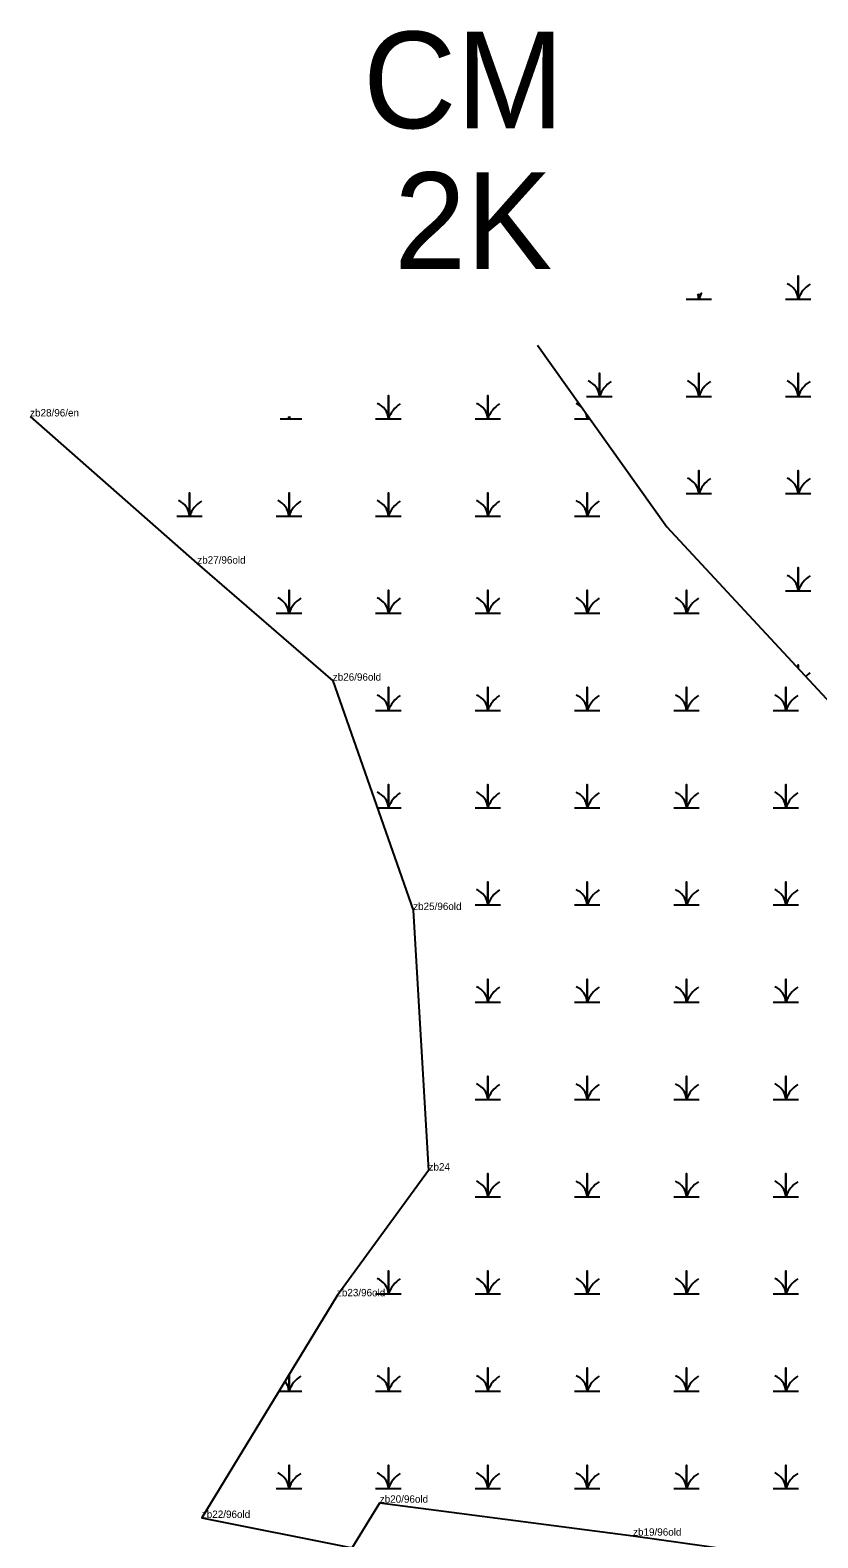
# Model space of a CAD drawing. Extents: x 2072529 to 2268796, y 436423 to 470406.
# Drawn here: x 2251149 to 2251682, y 438852 to 439872 of the extents above; entities that cross this region are included whole.
import ezdxf

# ---------------------------------------------------------------- set-up
doc = ezdxf.new("R2010")
doc.units = 0
for name, color, linetype in [('Default', 7, 'Continuous'), ('Exist Environmental Wetland Boundary', 7, 'Continuous'), ('Exist Environmental Wetland Boundary Cogo Comment', 7, 'Continuous'), ('Exist Hydro Jurisdictional Stream or Body of Water NEU Mitigable', 7, 'Continuous'), ('Exist Hydro Swamp or Marsh', 7, 'Continuous'), ('Old_Level_20', 7, 'Continuous')]:
    doc.layers.add(name, color=color, linetype=linetype)

msp = doc.modelspace()

# ---------------------------------------------------------------- linework, layer by layer
at = {"layer": 'Exist Environmental Wetland Boundary'}
msp.add_lwpolyline([(2251148.9, 439610.5), (2251262, 439510.9), (2251353.7, 439431.7), (2251408.1, 439276.5), (2251418.5, 439100.2), (2251356.5, 439015.1), (2251265.1, 438865.1), (2251366.8, 438844.8), (2251385.5, 438875.4), (2251556.9, 438853.1), (2251718.8, 438830.1), (2251868.4, 438640), (2251940.7, 438572.9), (2252098.5, 438426.7), (2252083, 438409.3), (2252090.3, 438402.8), (2252096.8, 438411.4), (2252129.6, 438370.7)], dxfattribs=at)
at = {"layer": 'Exist Hydro Jurisdictional Stream or Body of Water NEU Mitigable'}
for p, q in [((2251492.3, 439658.8), (2251579.7, 439535.8)), ((2251579.7, 439535.8), (2251746.6, 439355.9))]:
    msp.add_line(p, q, dxfattribs=at)
at = {"layer": 'Exist Hydro Swamp or Marsh'}
for points in [[(2251660, 439689.9), (2251668.6, 439689.9), (2251668.6, 439705.6), (2251668.6, 439689.9), (2251677.2, 439689.9)], [(2251592.8, 439689.9), (2251601.4, 439689.9), (2251601.4, 439693.5)], [(2251601.4, 439693.5), (2251601.4, 439689.9), (2251610, 439689.9)], [(2251525.5, 439624.1), (2251534.1, 439624.1), (2251534.1, 439639.8), (2251534.1, 439624.1), (2251542.7, 439624.1)], [(2251592.8, 439624.1), (2251601.4, 439624.1), (2251601.4, 439639.8), (2251601.4, 439624.1), (2251610, 439624.1)], [(2251660, 439624.1), (2251668.6, 439624.1), (2251668.6, 439639.8), (2251668.6, 439624.1), (2251677.2, 439624.1)], [(2251382.7, 439608.9), (2251391.3, 439608.9), (2251391.3, 439624.6), (2251391.3, 439608.9), (2251399.9, 439608.9)], [(2251450, 439608.9), (2251458.6, 439608.9), (2251458.6, 439624.6), (2251458.6, 439608.9), (2251467.2, 439608.9)], [(2251318.1, 439608.9), (2251324.1, 439608.9), (2251324.1, 439610.4)], [(2251324.1, 439610.4), (2251324.1, 439608.9), (2251332.7, 439608.9)], [(2251517.2, 439608.9), (2251525.8, 439608.9), (2251525.8, 439611.6)], [(2251525.8, 439611.6), (2251525.8, 439608.9), (2251527.8, 439608.9)], [(2251592.8, 439558.3), (2251601.4, 439558.3), (2251601.4, 439574), (2251601.4, 439558.3), (2251610, 439558.3)], [(2251660, 439558.3), (2251668.6, 439558.3), (2251668.6, 439574), (2251668.6, 439558.3), (2251677.2, 439558.3)], [(2251248.2, 439543.1), (2251256.8, 439543.1), (2251256.8, 439558.8), (2251256.8, 439543.1), (2251265.4, 439543.1)], [(2251315.5, 439543.1), (2251324.1, 439543.1), (2251324.1, 439558.8), (2251324.1, 439543.1), (2251332.7, 439543.1)], [(2251382.7, 439543.1), (2251391.3, 439543.1), (2251391.3, 439558.8), (2251391.3, 439543.1), (2251399.9, 439543.1)], [(2251450, 439543.1), (2251458.6, 439543.1), (2251458.6, 439558.8), (2251458.6, 439543.1), (2251467.2, 439543.1)], [(2251517.2, 439543.1), (2251525.8, 439543.1), (2251525.8, 439558.8), (2251525.8, 439543.1), (2251534.4, 439543.1)], [(2251660, 439492.5), (2251668.6, 439492.5), (2251668.6, 439508.2), (2251668.6, 439492.5), (2251677.2, 439492.5)], [(2251315.5, 439477.3), (2251324.1, 439477.3), (2251324.1, 439493), (2251324.1, 439477.3), (2251332.7, 439477.3)], [(2251382.7, 439477.3), (2251391.3, 439477.3), (2251391.3, 439493), (2251391.3, 439477.3), (2251399.9, 439477.3)], [(2251450, 439477.3), (2251458.6, 439477.3), (2251458.6, 439493), (2251458.6, 439477.3), (2251467.2, 439477.3)], [(2251517.2, 439477.3), (2251525.8, 439477.3), (2251525.8, 439493), (2251525.8, 439477.3), (2251534.4, 439477.3)], [(2251584.5, 439477.3), (2251593.1, 439477.3), (2251593.1, 439493), (2251593.1, 439477.3), (2251601.7, 439477.3)], [(2251668.6, 439440), (2251668.6, 439442.4), (2251668.6, 439440)], [(2251382.7, 439411.5), (2251391.3, 439411.5), (2251391.3, 439427.2), (2251391.3, 439411.5), (2251399.9, 439411.5)], [(2251450, 439411.5), (2251458.6, 439411.5), (2251458.6, 439427.2), (2251458.6, 439411.5), (2251467.2, 439411.5)], [(2251517.2, 439411.5), (2251525.8, 439411.5), (2251525.8, 439427.2), (2251525.8, 439411.5), (2251534.4, 439411.5)], [(2251584.5, 439411.5), (2251593.1, 439411.5), (2251593.1, 439427.2), (2251593.1, 439411.5), (2251601.7, 439411.5)], [(2251651.7, 439411.5), (2251660.3, 439411.5), (2251660.3, 439427.2), (2251660.3, 439411.5), (2251668.9, 439411.5)], [(2251383.8, 439345.7), (2251391.3, 439345.7), (2251391.3, 439361.4), (2251391.3, 439345.7), (2251399.9, 439345.7)], [(2251450, 439345.7), (2251458.6, 439345.7), (2251458.6, 439361.4), (2251458.6, 439345.7), (2251467.2, 439345.7)], [(2251517.2, 439345.7), (2251525.8, 439345.7), (2251525.8, 439361.4), (2251525.8, 439345.7), (2251534.4, 439345.7)], [(2251584.5, 439345.7), (2251593.1, 439345.7), (2251593.1, 439361.4), (2251593.1, 439345.7), (2251601.7, 439345.7)], [(2251651.7, 439345.7), (2251660.3, 439345.7), (2251660.3, 439361.4), (2251660.3, 439345.7), (2251668.9, 439345.7)], [(2251450, 439279.9), (2251458.6, 439279.9), (2251458.6, 439295.6), (2251458.6, 439279.9), (2251467.2, 439279.9)], [(2251517.2, 439279.9), (2251525.8, 439279.9), (2251525.8, 439295.6), (2251525.8, 439279.9), (2251534.4, 439279.9)], [(2251584.5, 439279.9), (2251593.1, 439279.9), (2251593.1, 439295.6), (2251593.1, 439279.9), (2251601.7, 439279.9)], [(2251651.7, 439279.9), (2251660.3, 439279.9), (2251660.3, 439295.6), (2251660.3, 439279.9), (2251668.9, 439279.9)], [(2251450, 439214.1), (2251458.6, 439214.1), (2251458.6, 439229.8), (2251458.6, 439214.1), (2251467.2, 439214.1)], [(2251517.2, 439214.1), (2251525.8, 439214.1), (2251525.8, 439229.8), (2251525.8, 439214.1), (2251534.4, 439214.1)], [(2251584.5, 439214.1), (2251593.1, 439214.1), (2251593.1, 439229.8), (2251593.1, 439214.1), (2251601.7, 439214.1)], [(2251651.7, 439214.1), (2251660.3, 439214.1), (2251660.3, 439229.8), (2251660.3, 439214.1), (2251668.9, 439214.1)], [(2251450, 439148.3), (2251458.6, 439148.3), (2251458.6, 439164), (2251458.6, 439148.3), (2251467.2, 439148.3)], [(2251517.2, 439148.3), (2251525.8, 439148.3), (2251525.8, 439164), (2251525.8, 439148.3), (2251534.4, 439148.3)], [(2251584.5, 439148.3), (2251593.1, 439148.3), (2251593.1, 439164), (2251593.1, 439148.3), (2251601.7, 439148.3)], [(2251651.7, 439148.3), (2251660.3, 439148.3), (2251660.3, 439164), (2251660.3, 439148.3), (2251668.9, 439148.3)], [(2251450, 439082.5), (2251458.6, 439082.5), (2251458.6, 439098.2), (2251458.6, 439082.5), (2251467.2, 439082.5)], [(2251517.2, 439082.5), (2251525.8, 439082.5), (2251525.8, 439098.2), (2251525.8, 439082.5), (2251534.4, 439082.5)], [(2251584.5, 439082.5), (2251593.1, 439082.5), (2251593.1, 439098.2), (2251593.1, 439082.5), (2251601.7, 439082.5)], [(2251651.7, 439082.5), (2251660.3, 439082.5), (2251660.3, 439098.2), (2251660.3, 439082.5), (2251668.9, 439082.5)], [(2251382.7, 439016.7), (2251391.3, 439016.7), (2251391.3, 439032.4), (2251391.3, 439016.7), (2251399.9, 439016.7)], [(2251450, 439016.7), (2251458.6, 439016.7), (2251458.6, 439032.4), (2251458.6, 439016.7), (2251467.2, 439016.7)], [(2251517.2, 439016.7), (2251525.8, 439016.7), (2251525.8, 439032.4), (2251525.8, 439016.7), (2251534.4, 439016.7)], [(2251584.5, 439016.7), (2251593.1, 439016.7), (2251593.1, 439032.4), (2251593.1, 439016.7), (2251601.7, 439016.7)], [(2251651.7, 439016.7), (2251660.3, 439016.7), (2251660.3, 439032.4), (2251660.3, 439016.7), (2251668.9, 439016.7)], [(2251382.7, 438950.9), (2251391.3, 438950.9), (2251391.3, 438966.6), (2251391.3, 438950.9), (2251399.9, 438950.9)], [(2251450, 438950.9), (2251458.6, 438950.9), (2251458.6, 438966.6), (2251458.6, 438950.9), (2251467.2, 438950.9)], [(2251517.2, 438950.9), (2251525.8, 438950.9), (2251525.8, 438966.6), (2251525.8, 438950.9), (2251534.4, 438950.9)], [(2251584.5, 438950.9), (2251593.1, 438950.9), (2251593.1, 438966.6), (2251593.1, 438950.9), (2251601.7, 438950.9)], [(2251651.7, 438950.9), (2251660.3, 438950.9), (2251660.3, 438966.6), (2251660.3, 438950.9), (2251668.9, 438950.9)], [(2251317.3, 438950.9), (2251324.1, 438950.9), (2251324.1, 438961.9)], [(2251324.1, 438961.9), (2251324.1, 438950.9), (2251332.7, 438950.9)], [(2251315.5, 438885.1), (2251324.1, 438885.1), (2251324.1, 438900.8), (2251324.1, 438885.1), (2251332.7, 438885.1)], [(2251382.7, 438885.1), (2251391.3, 438885.1), (2251391.3, 438900.8), (2251391.3, 438885.1), (2251399.9, 438885.1)], [(2251450, 438885.1), (2251458.6, 438885.1), (2251458.6, 438900.8), (2251458.6, 438885.1), (2251467.2, 438885.1)], [(2251517.2, 438885.1), (2251525.8, 438885.1), (2251525.8, 438900.8), (2251525.8, 438885.1), (2251534.4, 438885.1)], [(2251584.5, 438885.1), (2251593.1, 438885.1), (2251593.1, 438900.8), (2251593.1, 438885.1), (2251601.7, 438885.1)], [(2251651.7, 438885.1), (2251660.3, 438885.1), (2251660.3, 438900.8), (2251660.3, 438885.1), (2251668.9, 438885.1)]]:
    msp.add_lwpolyline(points, dxfattribs=at)
for centre, radius, start, end in [((2251589.1, 439689), 12.3, 4.1403, 20.6339), ((2251619.6, 439683.8), 19.2, 147.1842, 161.6222), ((2251656.4, 439689), 12.3, 4.1403, 67.535), ((2251686.9, 439683.8), 19.2, 122.1274, 161.6222), ((2251521.9, 439623.2), 12.3, 4.1403, 67.535), ((2251552.4, 439618), 19.2, 122.1274, 161.6222), ((2251589.1, 439623.2), 12.3, 4.1403, 67.535), ((2251619.6, 439618), 19.2, 122.1274, 161.6222), ((2251656.4, 439623.2), 12.3, 4.1403, 67.535), ((2251686.9, 439618), 19.2, 122.1274, 161.6222), ((2251379.1, 439608), 12.3, 4.1403, 67.535), ((2251409.6, 439602.8), 19.2, 122.1274, 161.6222), ((2251446.3, 439608), 12.3, 4.1403, 67.535), ((2251476.8, 439602.8), 19.2, 122.1274, 161.6222), ((2251513.6, 439608), 12.3, 45.4287, 67.535), ((2251311.8, 439608), 12.3, 4.1403, 10.9704), ((2251342.3, 439602.8), 19.2, 156.2744, 161.6222), ((2251513.6, 439608), 12.3, 4.1403, 25.3582), ((2251544.1, 439602.8), 19.2, 155.9212, 161.6222), ((2251589.1, 439557.4), 12.3, 4.1403, 67.535), ((2251619.6, 439552.2), 19.2, 122.1274, 161.6222), ((2251656.4, 439557.4), 12.3, 4.1403, 67.535), ((2251686.9, 439552.2), 19.2, 122.1274, 161.6222), ((2251244.6, 439542.2), 12.3, 4.1403, 67.535), ((2251275.1, 439537), 19.2, 122.1274, 161.6222), ((2251311.8, 439542.2), 12.3, 4.1403, 67.535), ((2251342.3, 439537), 19.2, 122.1274, 161.6222), ((2251379.1, 439542.2), 12.3, 4.1403, 67.535), ((2251409.6, 439537), 19.2, 122.1274, 161.6222), ((2251446.3, 439542.2), 12.3, 4.1403, 67.535), ((2251476.8, 439537), 19.2, 122.1274, 161.6222), ((2251513.6, 439542.2), 12.3, 4.1403, 67.535), ((2251544.1, 439537), 19.2, 122.1274, 161.6222), ((2251656.4, 439491.6), 12.3, 4.1403, 67.535), ((2251686.9, 439486.4), 19.2, 122.1274, 161.6222), ((2251311.8, 439476.4), 12.3, 4.1403, 67.535), ((2251342.3, 439471.2), 19.2, 122.1274, 161.6222), ((2251379.1, 439476.4), 12.3, 4.1403, 67.535), ((2251409.6, 439471.2), 19.2, 122.1274, 161.6222), ((2251446.3, 439476.4), 12.3, 4.1403, 67.535), ((2251476.8, 439471.2), 19.2, 122.1274, 161.6222), ((2251513.6, 439476.4), 12.3, 4.1403, 67.535), ((2251544.1, 439471.2), 19.2, 122.1274, 161.6222), ((2251580.8, 439476.4), 12.3, 4.1403, 67.535), ((2251611.3, 439471.2), 19.2, 122.1274, 161.6222), ((2251686.9, 439420.6), 19.2, 122.1274, 133.4343), ((2251379.1, 439410.6), 12.3, 4.1403, 67.535), ((2251409.6, 439405.4), 19.2, 122.1274, 161.6222), ((2251446.3, 439410.6), 12.3, 4.1403, 67.535), ((2251476.8, 439405.4), 19.2, 122.1274, 161.6222), ((2251513.6, 439410.6), 12.3, 4.1403, 67.535), ((2251544.1, 439405.4), 19.2, 122.1274, 161.6222), ((2251580.8, 439410.6), 12.3, 4.1403, 67.535), ((2251611.3, 439405.4), 19.2, 122.1274, 161.6222), ((2251648.1, 439410.6), 12.3, 4.1403, 67.535), ((2251678.6, 439405.4), 19.2, 122.1274, 161.6222), ((2251379.1, 439344.8), 12.3, 4.1403, 67.535), ((2251409.6, 439339.6), 19.2, 122.1274, 161.6222), ((2251446.3, 439344.8), 12.3, 4.1403, 67.535), ((2251476.8, 439339.6), 19.2, 122.1274, 161.6222), ((2251513.6, 439344.8), 12.3, 4.1403, 67.535), ((2251544.1, 439339.6), 19.2, 122.1274, 161.6222), ((2251580.8, 439344.8), 12.3, 4.1403, 67.535), ((2251611.3, 439339.6), 19.2, 122.1274, 161.6222), ((2251648.1, 439344.8), 12.3, 4.1403, 67.535), ((2251678.6, 439339.6), 19.2, 122.1274, 161.6222), ((2251446.3, 439279), 12.3, 4.1403, 67.535), ((2251476.8, 439273.8), 19.2, 122.1274, 161.6222), ((2251513.6, 439279), 12.3, 4.1403, 67.535), ((2251544.1, 439273.8), 19.2, 122.1274, 161.6222), ((2251580.8, 439279), 12.3, 4.1403, 67.535), ((2251611.3, 439273.8), 19.2, 122.1274, 161.6222), ((2251648.1, 439279), 12.3, 4.1403, 67.535), ((2251678.6, 439273.8), 19.2, 122.1274, 161.6222), ((2251446.3, 439213.2), 12.3, 4.1403, 67.535), ((2251476.8, 439208), 19.2, 122.1274, 161.6222), ((2251513.6, 439213.2), 12.3, 4.1403, 67.535), ((2251544.1, 439208), 19.2, 122.1274, 161.6222), ((2251580.8, 439213.2), 12.3, 4.1403, 67.535), ((2251611.3, 439208), 19.2, 122.1274, 161.6222), ((2251648.1, 439213.2), 12.3, 4.1403, 67.535), ((2251678.6, 439208), 19.2, 122.1274, 161.6222), ((2251446.3, 439147.4), 12.3, 4.1403, 67.535), ((2251476.8, 439142.2), 19.2, 122.1274, 161.6222), ((2251513.6, 439147.4), 12.3, 4.1403, 67.535), ((2251544.1, 439142.2), 19.2, 122.1274, 161.6222), ((2251580.8, 439147.4), 12.3, 4.1403, 67.535), ((2251611.3, 439142.2), 19.2, 122.1274, 161.6222), ((2251648.1, 439147.4), 12.3, 4.1403, 67.535), ((2251678.6, 439142.2), 19.2, 122.1274, 161.6222), ((2251446.3, 439081.6), 12.3, 4.1403, 67.535), ((2251476.8, 439076.4), 19.2, 122.1274, 161.6222), ((2251513.6, 439081.6), 12.3, 4.1403, 67.535), ((2251544.1, 439076.4), 19.2, 122.1274, 161.6222), ((2251580.8, 439081.6), 12.3, 4.1403, 67.535), ((2251611.3, 439076.4), 19.2, 122.1274, 161.6222), ((2251648.1, 439081.6), 12.3, 4.1403, 67.535), ((2251678.6, 439076.4), 19.2, 122.1274, 161.6222), ((2251379.1, 439015.8), 12.3, 4.1403, 67.535), ((2251446.3, 439015.8), 12.3, 4.1403, 67.535), ((2251513.6, 439015.8), 12.3, 4.1403, 67.535), ((2251580.8, 439015.8), 12.3, 4.1403, 67.535), ((2251648.1, 439015.8), 12.3, 4.1403, 67.535), ((2251409.6, 439010.6), 19.2, 122.1274, 161.6222), ((2251476.8, 439010.6), 19.2, 122.1274, 161.6222), ((2251544.1, 439010.6), 19.2, 122.1274, 161.6222), ((2251611.3, 439010.6), 19.2, 122.1274, 161.6222), ((2251678.6, 439010.6), 19.2, 122.1274, 161.6222), ((2251311.8, 438950), 12.3, 4.1403, 38.437), ((2251342.3, 438944.8), 19.2, 122.1274, 161.6222), ((2251379.1, 438950), 12.3, 4.1403, 67.535), ((2251409.6, 438944.8), 19.2, 122.1274, 161.6222), ((2251446.3, 438950), 12.3, 4.1403, 67.535), ((2251476.8, 438944.8), 19.2, 122.1274, 161.6222), ((2251513.6, 438950), 12.3, 4.1403, 67.535), ((2251544.1, 438944.8), 19.2, 122.1274, 161.6222), ((2251580.8, 438950), 12.3, 4.1403, 67.535), ((2251611.3, 438944.8), 19.2, 122.1274, 161.6222), ((2251648.1, 438950), 12.3, 4.1403, 67.535), ((2251678.6, 438944.8), 19.2, 122.1274, 161.6222), ((2251311.8, 438884.2), 12.3, 4.1403, 67.535), ((2251342.3, 438879), 19.2, 122.1274, 161.6222), ((2251379.1, 438884.2), 12.3, 4.1403, 67.535), ((2251409.6, 438879), 19.2, 122.1274, 161.6222), ((2251446.3, 438884.2), 12.3, 4.1403, 67.535), ((2251476.8, 438879), 19.2, 122.1274, 161.6222), ((2251513.6, 438884.2), 12.3, 4.1403, 67.535), ((2251544.1, 438879), 19.2, 122.1274, 161.6222), ((2251580.8, 438884.2), 12.3, 4.1403, 67.535), ((2251611.3, 438879), 19.2, 122.1274, 161.6222), ((2251648.1, 438884.2), 12.3, 4.1403, 67.535), ((2251678.6, 438879), 19.2, 122.1274, 161.6222)]:
    msp.add_arc(centre, radius, start, end, dxfattribs=at)
at = {"layer": 'Old_Level_20'}
for p, q in [((2251148.9, 439610.5), (2251148.9, 439610.5)), ((2251262, 439510.9), (2251262, 439510.9)), ((2251353.7, 439431.7), (2251353.7, 439431.7)), ((2251408.1, 439276.5), (2251408.1, 439276.5)), ((2251418.5, 439100.2), (2251418.5, 439100.2)), ((2251356.5, 439015.1), (2251356.5, 439015.1)), ((2251385.5, 438875.4), (2251385.5, 438875.4)), ((2251265.1, 438865.1), (2251265.1, 438865.1)), ((2251556.9, 438853.1), (2251556.9, 438853.1))]:
    msp.add_line(p, q, dxfattribs=at)

# ---------------------------------------------------------------- texts
at = {"layer": 'Default'}
for s, p in [('CM', (2251374.2, 439805.6)), ('2K', (2251395.3, 439710.4))]:
    msp.add_text(s, height=65.34, dxfattribs=at).set_placement(p)
at = {"layer": 'Exist Environmental Wetland Boundary Cogo Comment'}
for s, p in [('zb28/96/en', (2251148.9, 439610.5)), ('zb27/96old', (2251262, 439510.9)), ('zb26/96old', (2251353.7, 439431.7)), ('zb25/96old', (2251408.1, 439276.5)), ('zb24', (2251418.5, 439100.2)), ('zb23/96old', (2251356.5, 439015.1)), ('zb20/96old', (2251385.5, 438875.4)), ('zb22/96old', (2251265.1, 438865.1)), ('zb19/96old', (2251556.9, 438853.1))]:
    msp.add_text(s, height=5, dxfattribs=at).set_placement(p)

doc.saveas('drawing.dxf')
